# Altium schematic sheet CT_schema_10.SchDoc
size 278 x 170 mm
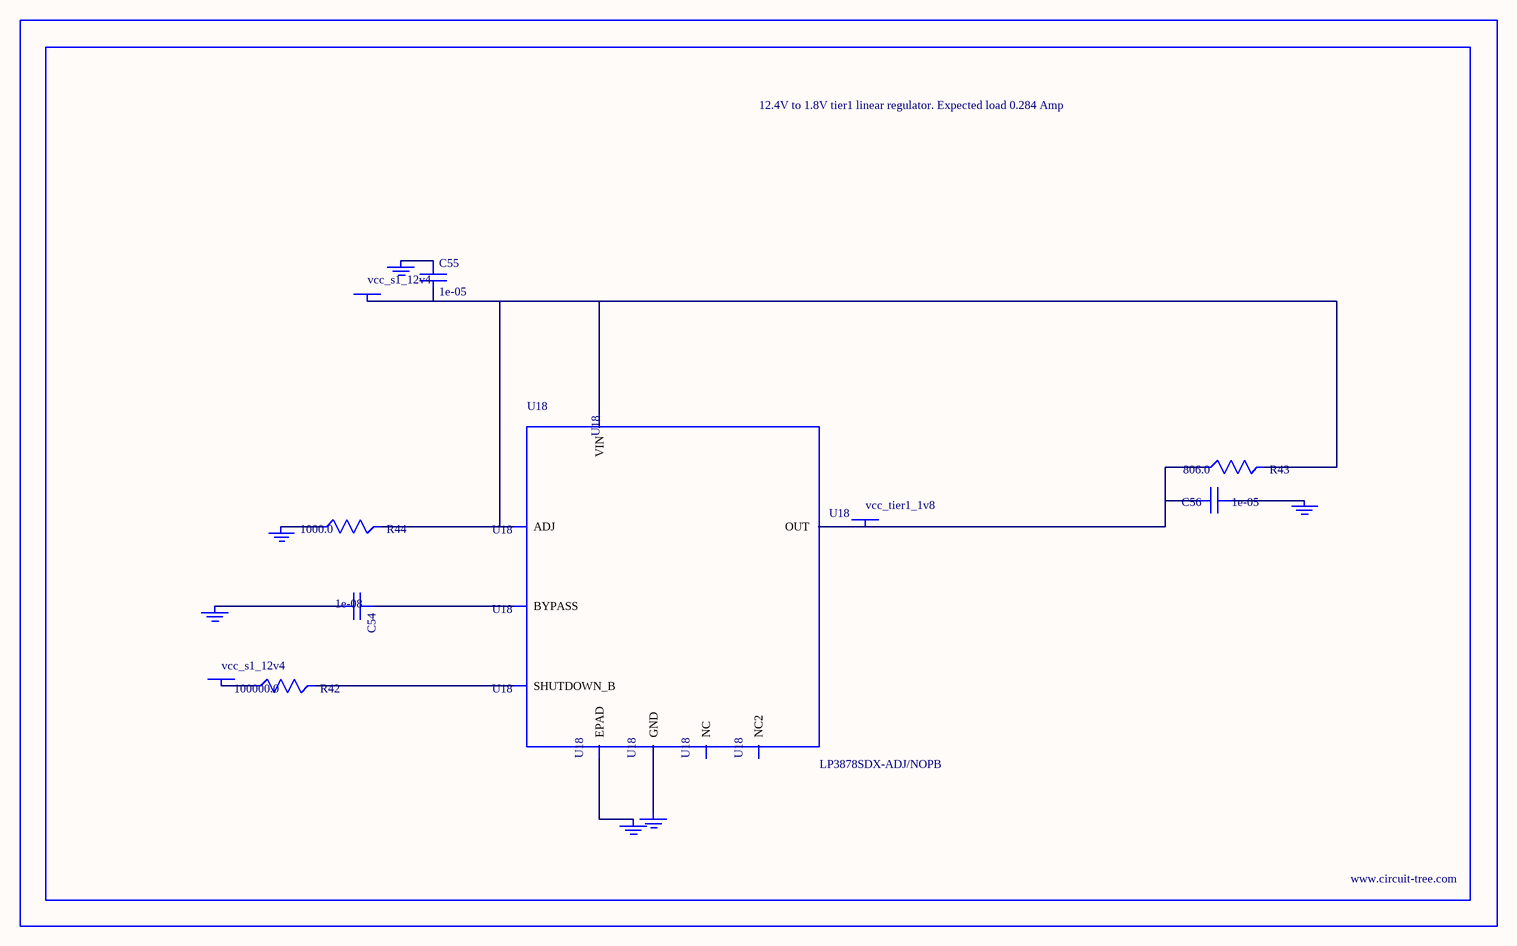
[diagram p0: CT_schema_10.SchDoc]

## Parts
BORDER9  (no value)
C54  1e-08  [C0402]
C55  1e-05  [C1210]
C56  1e-05  [C0805]
GND_INSTANCE_9_0  (no value)
GND_INSTANCE_9_1  (no value)
GND_INSTANCE_9_2  (no value)
GND_INSTANCE_9_3  (no value)
GND_INSTANCE_9_4  (no value)
GND_INSTANCE_9_5  (no value)
POWER_INSTANCE_9_0  vcc_s1_12v4
POWER_INSTANCE_9_1  vcc_s1_12v4
POWER_INSTANCE_9_2  vcc_tier1_1v8
R42  100000.0  [R0603]
R43  806.0  [R0603]
R44  1000.0  [R0603]
U18  LP3878SDX-ADJ/NOPB  [WSON-8]

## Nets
NetC54_1: C54.1 U18.1(BYPASS)
NetC54_2: C54.2 GND_INSTANCE_9_0.0(GND)
NetC55_1: C55.1 GND_INSTANCE_9_1.0(GND)
NetC55_2: C55.2 POWER_INSTANCE_9_0.0(PWR) R43.2 R44.2 U18.4(VIN) U18.6(ADJ)
NetC56_1: C56.1 GND_INSTANCE_9_2.0(GND)
NetC56_2: C56.2 POWER_INSTANCE_9_2.0(PWR) R43.1 U18.5(OUT)
NetGND_INSTANCE_9_3_0: GND_INSTANCE_9_3.0(GND) R44.1
NetGND_INSTANCE_9_4_0: GND_INSTANCE_9_4.0(GND) U18.PAD(EPAD)
NetGND_INSTANCE_9_5_0: GND_INSTANCE_9_5.0(GND) U18.3(GND)
NetPOWER_INSTANCE_9_1_0: POWER_INSTANCE_9_1.0(PWR) R42.1
NetR42_2: R42.2 U18.8(SHUTDOWN_B)

Not connected (* = marked no-connect by the designer): U18 2(NC) 7(NC2)

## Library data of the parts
BORDER9 = BORDER_PAGE9
C54 = C0402C103K3RAC
C55 = C1210C106K5PACTU
C56 = GRM219R60J106ME19D
GND_INSTANCE_9_0-GND_INSTANCE_9_5 = GND
POWER_INSTANCE_9_0-POWER_INSTANCE_9_2 = PWR
R42 = RC0603JR-07100KL
R43 = ERJ-3EKF8060V
R44 = RC0603JR-071KL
